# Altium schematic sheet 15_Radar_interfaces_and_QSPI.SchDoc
size 289 x 396 mm
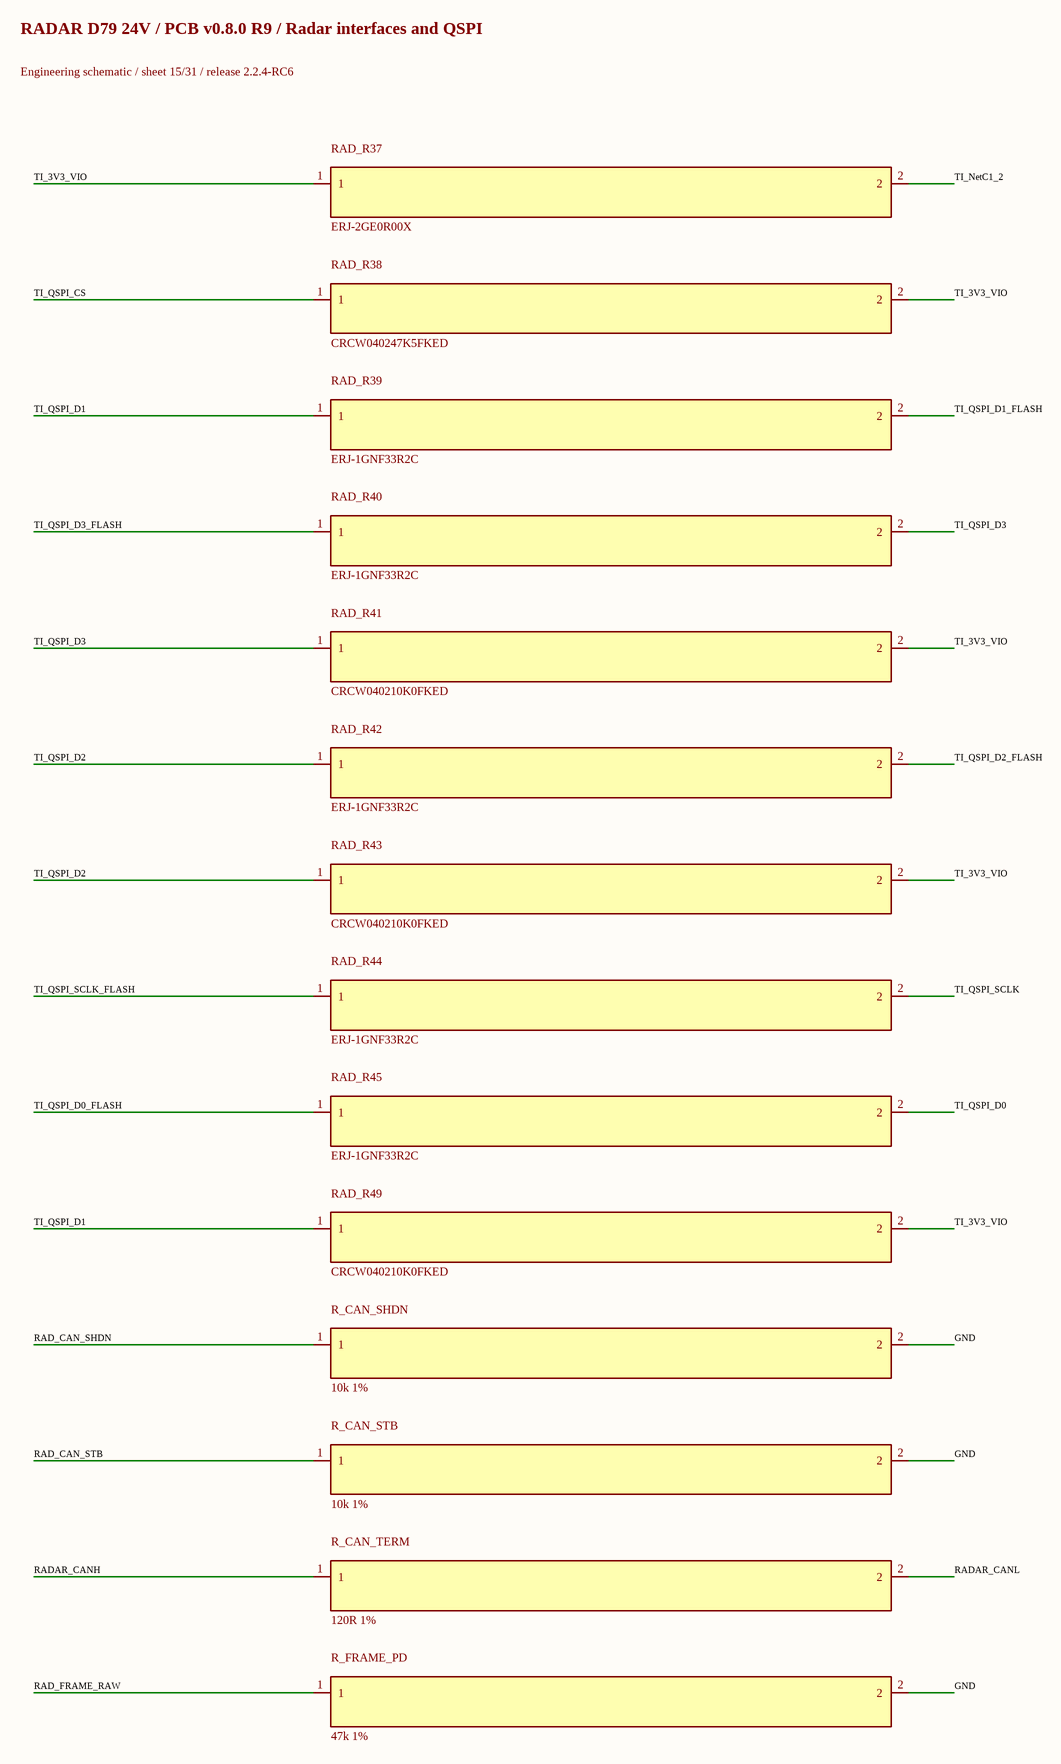
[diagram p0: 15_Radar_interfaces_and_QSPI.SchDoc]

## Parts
R_CAN_SHDN  10k 1%  [R_0603_1608Metric]
R_CAN_STB  10k 1%  [R_0603_1608Metric]
R_CAN_TERM  120R 1%  [R_0603_1608Metric]
R_FRAME_PD  47k 1%  [R_0603_1608Metric]
RAD_R37  ERJ-2GE0R00X  [0402L]
RAD_R38  CRCW040247K5FKED  [0402L]
RAD_R39  ERJ-1GNF33R2C  [FP-ERJ-1GNF33R2C_0201-MFG]
RAD_R40  ERJ-1GNF33R2C  [FP-ERJ-1GNF33R2C_0201-MFG]
RAD_R41  CRCW040210K0FKED  [0402L]
RAD_R42  ERJ-1GNF33R2C  [FP-ERJ-1GNF33R2C_0201-MFG]
RAD_R43  CRCW040210K0FKED  [0402L]
RAD_R44  ERJ-1GNF33R2C  [FP-ERJ-1GNF33R2C_0201-MFG]
RAD_R45  ERJ-1GNF33R2C  [FP-ERJ-1GNF33R2C_0201-MFG]
RAD_R49  CRCW040210K0FKED  [0402L]

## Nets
GND: R_CAN_SHDN.2 R_CAN_STB.2 R_FRAME_PD.2
RAD_CAN_SHDN: R_CAN_SHDN.1
RAD_CAN_STB: R_CAN_STB.1
RAD_FRAME_RAW: R_FRAME_PD.1
RADAR_CANH: R_CAN_TERM.1
RADAR_CANL: R_CAN_TERM.2
TI_3V3_VIO: RAD_R37.1 RAD_R38.2 RAD_R41.2 RAD_R43.2 RAD_R49.2
TI_NetC1_2: RAD_R37.2
TI_QSPI_CS: RAD_R38.1
TI_QSPI_D0: RAD_R45.2
TI_QSPI_D0_FLASH: RAD_R45.1
TI_QSPI_D1: RAD_R39.1 RAD_R49.1
TI_QSPI_D1_FLASH: RAD_R39.2
TI_QSPI_D2: RAD_R42.1 RAD_R43.1
TI_QSPI_D2_FLASH: RAD_R42.2
TI_QSPI_D3: RAD_R40.2 RAD_R41.1
TI_QSPI_D3_FLASH: RAD_R40.1
TI_QSPI_SCLK: RAD_R44.2
TI_QSPI_SCLK_FLASH: RAD_R44.1

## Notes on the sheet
- RADAR D79 24V / PCB v0.8.0 R9 / Radar interfaces and QSPI
- Engineering schematic / sheet 15/31 / release 2.2.4-RC6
